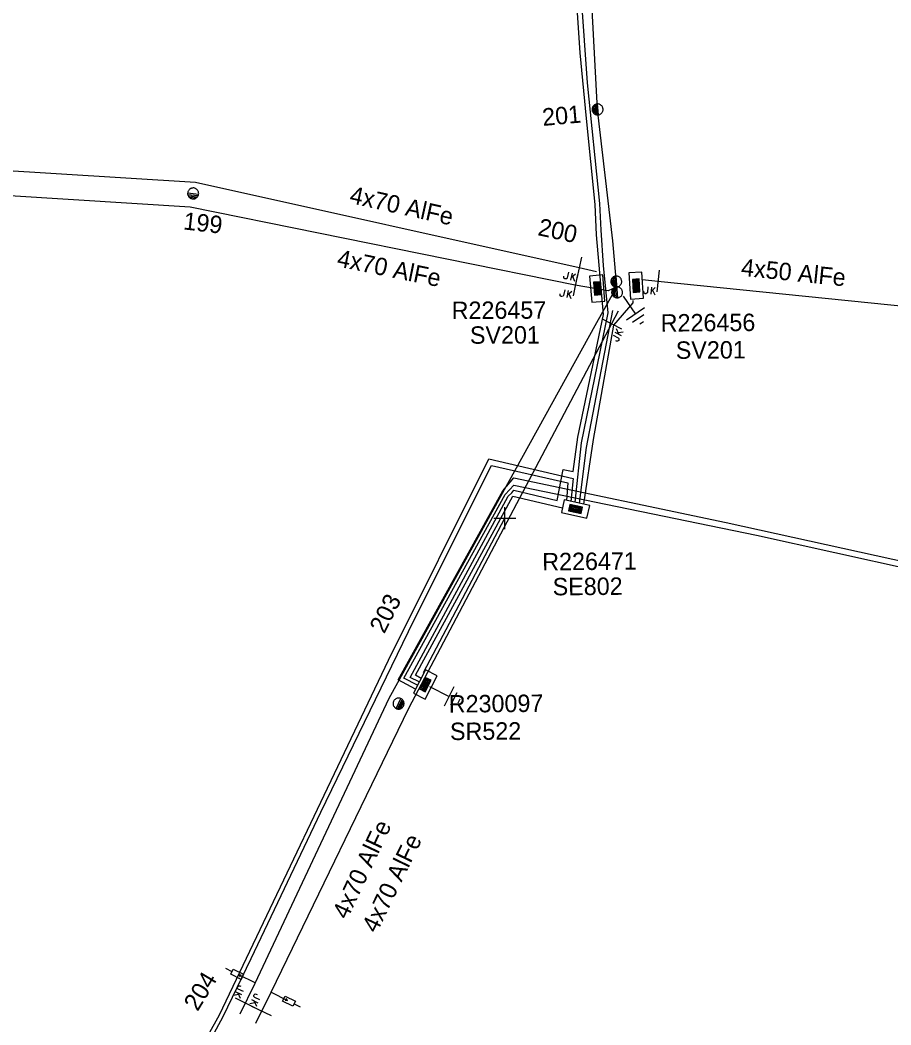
# Model space of a CAD drawing. Extents: x -544780 to -541582, y -1198995 to -1196551.
# Drawn here: x -542503.2 to -542453.2, y -1198617.5 to -1198559.8 of the extents above; entities that cross this region are included whole.
import ezdxf

# ---------------------------------------------------------------- set-up
doc = ezdxf.new("R2010")
doc.units = 0
for name, color, linetype in [('Vrstva 1', 7, 'Continuous'), ('Vrstva 13', 7, 'Continuous'), ('Vrstva 14', 7, 'Continuous'), ('Vrstva 15', 7, 'Continuous'), ('Vrstva 16', 7, 'Continuous'), ('Vrstva 18', 7, 'Continuous'), ('Vrstva 2', 7, 'Continuous'), ('Vrstva 28', 7, 'Continuous'), ('Vrstva 29', 7, 'Continuous'), ('Vrstva 30', 7, 'Continuous'), ('Vrstva 34', 7, 'Continuous'), ('Vrstva 5', 7, 'Continuous'), ('Vrstva 52', 7, 'Continuous'), ('Vrstva 8', 7, 'Continuous')]:
    doc.layers.add(name, color=color, linetype=linetype)

# ---------------------------------------------------------------- blocks, each defined once
blk = doc.blocks.new('NN440')
at = {"layer": 'Vrstva 2'}
for points in [[(0.63, 0), (0.63, 0.06), (0.62, 0.13), (0.6, 0.19), (0.58, 0.25), (0.55, 0.31), (0.51, 0.37), (0.47, 0.42), (0.42, 0.46), (0.37, 0.51), (0.32, 0.54), (0.26, 0.57), (0.2, 0.59), (0.13, 0.61), (0.07, 0.62), (0, 0.63), (-0.06, 0.62), (-0.13, 0.61), (-0.19, 0.59), (-0.26, 0.57), (-0.31, 0.54), (-0.37, 0.51), (-0.42, 0.46), (-0.47, 0.42), (-0.51, 0.37), (-0.54, 0.31), (-0.57, 0.25), (-0.6, 0.19), (-0.62, 0.13), (-0.63, 0.06), (-0.63, 0), (-0.63, -0.07), (-0.62, -0.14), (-0.6, -0.2), (-0.57, -0.26), (-0.54, -0.32), (-0.51, -0.37), (-0.47, -0.43), (-0.42, -0.47), (-0.37, -0.51), (-0.31, -0.55), (-0.26, -0.58), (-0.19, -0.6), (-0.13, -0.62), (-0.06, -0.63), (0, -0.63), (0.07, -0.63), (0.13, -0.62), (0.2, -0.6), (0.26, -0.58), (0.32, -0.55), (0.37, -0.51), (0.42, -0.47), (0.47, -0.43), (0.51, -0.37), (0.55, -0.32), (0.58, -0.26), (0.6, -0.2), (0.62, -0.14), (0.63, -0.07), (0.63, 0)], [(-0.63, 0), (0.63, 0)], [(-0.6, -0.18), (0.57, -0.18)], [(-0.51, -0.32), (0.5, -0.32)], [(-0.37, -0.47), (0.35, -0.47)]]:
    blk.add_lwpolyline(points, dxfattribs=at)
blk = doc.blocks.new('NN450')
at = {"layer": 'Vrstva 2'}
for points in [[(0, 0), (0, 0.07), (-0.01, 0.13), (-0.03, 0.19), (-0.05, 0.25), (-0.08, 0.31), (-0.12, 0.37), (-0.16, 0.42), (-0.21, 0.46), (-0.26, 0.51), (-0.31, 0.54), (-0.37, 0.57), (-0.43, 0.59), (-0.5, 0.61), (-0.56, 0.62), (-0.63, 0.62), (-0.69, 0.62), (-0.75, 0.61), (-0.82, 0.59), (-0.88, 0.57), (-0.94, 0.54), (-0.99, 0.51), (-1.04, 0.46), (-1.09, 0.42), (-1.13, 0.37), (-1.17, 0.31), (-1.2, 0.25), (-1.22, 0.19), (-1.24, 0.13), (-1.25, 0.07), (-1.25, 0), (-1.25, -0.07), (-1.24, -0.13), (-1.22, -0.19), (-1.2, -0.25), (-1.17, -0.31), (-1.13, -0.37), (-1.09, -0.42), (-1.04, -0.46), (-0.99, -0.51), (-0.94, -0.54), (-0.88, -0.57), (-0.82, -0.59), (-0.75, -0.61), (-0.69, -0.62), (-0.62, -0.63), (-0.56, -0.62), (-0.5, -0.61), (-0.43, -0.59), (-0.37, -0.57), (-0.31, -0.54), (-0.26, -0.51), (-0.21, -0.46), (-0.16, -0.42), (-0.12, -0.37), (-0.08, -0.31), (-0.05, -0.25), (-0.03, -0.19), (-0.01, -0.13), (0, -0.07), (0, 0)], [(1.25, 0), (1.25, 0.07), (1.24, 0.13), (1.22, 0.19), (1.2, 0.25), (1.17, 0.31), (1.13, 0.37), (1.09, 0.42), (1.04, 0.46), (0.99, 0.51), (0.94, 0.54), (0.88, 0.57), (0.82, 0.59), (0.75, 0.61), (0.69, 0.62), (0.62, 0.62), (0.56, 0.62), (0.5, 0.61), (0.43, 0.59), (0.37, 0.57), (0.31, 0.54), (0.26, 0.51), (0.21, 0.46), (0.16, 0.42), (0.12, 0.37), (0.08, 0.31), (0.05, 0.25), (0.03, 0.19), (0.01, 0.13), (0, 0.07), (0, 0), (0, -0.07), (0.01, -0.13), (0.03, -0.19), (0.05, -0.25), (0.08, -0.31), (0.12, -0.37), (0.16, -0.42), (0.21, -0.46), (0.26, -0.51), (0.31, -0.54), (0.37, -0.57), (0.43, -0.59), (0.5, -0.61), (0.56, -0.62), (0.63, -0.63), (0.69, -0.62), (0.75, -0.61), (0.82, -0.59), (0.88, -0.57), (0.94, -0.54), (0.99, -0.51), (1.04, -0.46), (1.09, -0.42), (1.13, -0.37), (1.17, -0.31), (1.2, -0.25), (1.22, -0.19), (1.24, -0.13), (1.25, -0.07), (1.25, 0)], [(-1.25, 0), (1.25, 0)], [(-1.23, -0.16), (-0.02, -0.16)], [(-1.16, -0.32), (-0.09, -0.32)], [(-1.03, -0.47), (-0.22, -0.47)], [(0.02, -0.16), (1.23, -0.16)], [(0.09, -0.32), (1.16, -0.32)], [(0.22, -0.47), (1.03, -0.47)]]:
    blk.add_lwpolyline(points, dxfattribs=at)
blk = doc.blocks.new('NN840')
at = {"layer": 'Vrstva 15'}
for points in [[(0.003, 0.619), (0.003, -0.631)], [(-0.538, -0.385), (-0.538, -0.71)], [(-0.332, -0.385), (-0.332, -0.798)], [(-0.332, -0.641), (-0.125, -0.385)], [(-0.263, -0.557), (-0.091, -0.798)], [(-0.745, -0.71), (-0.745, -0.66)], [(-0.73, -0.764), (-0.745, -0.71)], [(-0.657, -0.798), (-0.73, -0.764)], [(-0.627, -0.798), (-0.657, -0.798)], [(-0.558, -0.764), (-0.627, -0.798)], [(-0.538, -0.71), (-0.558, -0.764)]]:
    blk.add_lwpolyline(points, dxfattribs=at)
blk = doc.blocks.new('NN800')
at = {"layer": 'Vrstva 1'}
for points in [[(-0.442, 0.442), (0.442, -0.442)], [(-0.442, -0.442), (0.442, 0.442)]]:
    blk.add_lwpolyline(points, dxfattribs=at)
blk = doc.blocks.new('NN820')
at = {"layer": 'Vrstva 13'}
for points in [[(-0.003, 0.004), (-0.003, -1.049)], [(-0.165, -0.813), (0.165, -0.813)], [(-0.165, -1.473), (-0.165, -0.813)], [(-0.003, -1.049), (-0.062, -0.926)], [(-0.003, -1.049), (0.057, -0.926)], [(0.165, -0.813), (0.165, -1.473)], [(0.165, -1.473), (-0.165, -1.473)], [(-0.003, -1.473), (-0.003, -1.871)]]:
    blk.add_lwpolyline(points, dxfattribs=at)
blk = doc.blocks.new('NN620')
at = {"layer": 'Vrstva 8'}
for points in [[(0.752, 0.004), (-0.748, 0.004)], [(-0.748, 0.004), (-0.748, -0.746)], [(0.752, -0.746), (0.752, 0.004)], [(0.368, -0.18), (-0.376, -0.18)], [(-0.376, -0.18), (-0.376, -0.558)], [(-0.376, -0.558), (0.368, -0.558)], [(0.321, -0.227), (-0.329, -0.227)], [(-0.329, -0.227), (-0.329, -0.51)], [(-0.329, -0.51), (0.321, -0.51)], [(0.274, -0.274), (-0.281, -0.274)], [(-0.281, -0.274), (-0.281, -0.463)], [(-0.281, -0.463), (0.274, -0.463)], [(0.227, -0.321), (-0.234, -0.321)], [(-0.234, -0.321), (-0.234, -0.416)], [(-0.234, -0.416), (0.227, -0.416)], [(-0.193, -0.369), (0.185, -0.369)], [(0.227, -0.416), (0.227, -0.321)], [(0.274, -0.463), (0.274, -0.274)], [(0.321, -0.51), (0.321, -0.227)], [(0.368, -0.558), (0.368, -0.18)], [(-0.748, -0.746), (0.752, -0.746)]]:
    blk.add_lwpolyline(points, dxfattribs=at)
blk = doc.blocks.new('NN810')
at = {"layer": 'Vrstva 14'}
for points in [[(0.004, -0.64), (0.004, -1.89)], [(0.629, -1.89), (-0.621, -1.89)], [(0.388, -2.2), (-0.399, -2.2)], [(0.004, -2.515), (-0.124, -2.515)], [(0.137, -2.515), (0.004, -2.515)]]:
    blk.add_lwpolyline(points, dxfattribs=at)

msp = doc.modelspace()

# ---------------------------------------------------------------- linework, layer by layer
at = {"layer": 'Vrstva 1'}
for points in [[(-542468.937, -1198575.165), (-542469.166, -1198572.51), (-542470.032, -1198564.977), (-542470.578, -1198554.925)], [(-542468.937, -1198575.165), (-542469.418, -1198575.393), (-542471.312, -1198575.063), (-542493.418, -1198570.581), (-542520.821, -1198568.867), (-542547.289, -1198568.867), (-542573.951, -1198565.092), (-542607.008, -1198561.88), (-542636.019, -1198560.809), (-542636.996, -1198560.774)], [(-542470.089, -1198574.29), (-542471.092, -1198574.066), (-542493.107, -1198569.179), (-542520.509, -1198567.465)], [(-542467.456, -1198574.735), (-542466.568, -1198574.826), (-542449.621, -1198576.557), (-542436.372, -1198579.515), (-542423.343, -1198581.048), (-542395.641, -1198584.992), (-542374.333, -1198589.374)], [(-542490.551, -1198616.879), (-542489.69, -1198615.116), (-542482.003, -1198598.772), (-542470.082, -1198577.206), (-542468.937, -1198575.165)], [(-542489.653, -1198617.421), (-542488.766, -1198615.646), (-542480.869, -1198599.347), (-542468.84, -1198576.539)]]:
    msp.add_lwpolyline(points, dxfattribs=at)
at = {"layer": 'Vrstva 5'}
for points in [[(-542480.281, -1198597.836), (-542480.799, -1198597.58), (-542475.157, -1198587.174), (-542474.962, -1198586.979), (-542474.841, -1198586.833), (-542472.359, -1198587.417), (-542472.011, -1198585.635), (-542471.444, -1198585.756), (-542471.171, -1198583.794), (-542469.689, -1198576.743), (-542470.102, -1198572.18), (-542470.175, -1198570.429), (-542470.661, -1198565.504), (-542471.025, -1198561.735), (-542471.536, -1198554.257), (-542469.786, -1198554.159)], [(-542471.319, -1198587.525), (-542470.952, -1198584.11), (-542469.421, -1198576.646), (-542469.689, -1198573.931), (-542469.834, -1198571.913), (-542469.907, -1198570.383), (-542470.612, -1198563.443), (-542471.122, -1198556.149), (-542471.171, -1198553.969), (-542469.81, -1198553.872)], [(-542470.82, -1198587.636), (-542470.272, -1198583.912), (-542469.105, -1198577.355), (-542467.996, -1198576.068), (-542467.998, -1198575.935)], [(-542471.068, -1198587.579), (-542470.661, -1198584.378), (-542469.158, -1198576.525)], [(-542484.072, -1198642.566), (-542501.191, -1198635.632), (-542494.981, -1198622.783), (-542491.725, -1198616.948), (-542482.038, -1198596.585), (-542476.266, -1198585.023), (-542471.428, -1198586.153), (-542471.567, -1198587.471)], [(-542484.042, -1198642.27), (-542500.865, -1198635.484), (-542497.636, -1198628.837), (-542495.089, -1198623.592), (-542493.441, -1198620.587), (-542491.516, -1198617.031), (-542489.917, -1198613.712), (-542485.918, -1198605.313), (-542480.587, -1198594.303), (-542476.126, -1198585.416), (-542471.735, -1198586.413), (-542471.819, -1198587.417)], [(-542480.489, -1198598.259), (-542481.478, -1198597.718), (-542475.48, -1198586.87), (-542474.848, -1198586.116), (-542462.649, -1198588.693), (-542441.447, -1198593.362), (-542417.555, -1198596.786), (-542417.319, -1198595.161), (-542417.246, -1198594.966), (-542410.733, -1198596.133), (-542397.624, -1198598.37), (-542381.307, -1198601.233), (-542362.61, -1198604.536), (-542349.307, -1198606.915), (-542336.927, -1198609.151), (-542337.121, -1198610.221)], [(-542480.374, -1198598.027), (-542481.153, -1198597.621), (-542475.342, -1198587.07), (-542474.831, -1198586.535), (-542469.558, -1198587.63), (-542460.907, -1198589.405), (-542451.924, -1198591.398)], [(-542480.164, -1198597.63), (-542480.476, -1198597.439), (-542474.889, -1198587.17), (-542472.054, -1198587.837)]]:
    msp.add_lwpolyline(points, dxfattribs=at)
at = {"layer": 'Vrstva 52'}
msp.add_lwpolyline([(-542480.026, -1198597.289), (-542475.355, -1198588.438)], dxfattribs=at)

# ---------------------------------------------------------------- block references
at = {"layer": 'Vrstva 13'}
for name, p, xscale, yscale, rotation in [('NN440', (-542470.032, -1198564.977), 0.49999999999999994, 0.5000000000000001, -84.91075002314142), ('NN440', (-542493.244, -1198569.797), 0.5, 0.5, -6.524602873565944), ('NN450', (-542468.937, -1198575.165), 0.5, 0.5, -85.85884440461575), ('NN440', (-542481.459, -1198599.079), 0.5000000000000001, 0.5000000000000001, 63.98582776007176)]:
    msp.add_blockref(name, p, dxfattribs=dict(at, xscale=xscale, yscale=yscale, rotation=rotation))
at = {"layer": 'Vrstva 15'}
for p, rotation in [((-542468.938, -1198575.165), 34.452369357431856), ((-542480.25, -1198597.82), 63.23083060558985)]:
    msp.add_blockref('NN810', p, dxfattribs=dict(at, rotation=rotation))
at = {"layer": 'Vrstva 16'}
for p, rotation in [((-542489.69, -1198615.116), -116.04254448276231), ((-542488.766, -1198615.646), 63.455255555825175)]:
    msp.add_blockref('NN820', p, dxfattribs=dict(at, rotation=rotation))
at = {"layer": 'Vrstva 18'}
for p, rotation in [((-542471.092, -1198574.066), -12.51805277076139), ((-542471.312, -1198575.063), -11.462030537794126), ((-542466.568, -1198574.826), -5.832597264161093), ((-542469.227, -1198577.285), 62.54138613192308), ((-542490.251, -1198616.264), -116.04254448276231), ((-542489.309, -1198616.735), -115.84929448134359)]:
    msp.add_blockref('NN840', p, dxfattribs=dict(at, rotation=rotation))
at = {"layer": 'Vrstva 28'}
for p, rotation in [((-542469.685, -1198575.225), -85.38000000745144), ((-542468.188, -1198575.113), 93.94400004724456), ((-542471.22, -1198587.548), -12.2806918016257), ((-542480.25, -1198597.82), 63.23083060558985)]:
    msp.add_blockref('NN620', p, dxfattribs=dict(at, rotation=rotation))
at = {"layer": 'Vrstva 34', "rotation": 45}
msp.add_blockref('NN800', (-542475.355, -1198588.438), dxfattribs=at)

# ---------------------------------------------------------------- texts
at = {"layer": 'Vrstva 14'}
for s, rotation, p in [('201', 5.089, (-542473.166, -1198565.926)), ('199', 353.475, (-542493.843, -1198571.859)), ('200', 347.833, (-542473.512, -1198572.186)), ('203', 63.231, (-542482.276, -1198595.114)), ('204', 58.693, (-542492.989, -1198616.787))]:
    msp.add_text(s, height=1, rotation=rotation, dxfattribs=at).set_placement(p)
at = {"layer": 'Vrstva 2'}
for s, rotation, p in [('4x70 AlFe', 347.484, (-542484.321, -1198570.336)), ('4x70 AlFe', 348.539, (-542485.039, -1198573.977)), ('4x50 AlFe', 354.168, (-542461.832, -1198574.52)), ('4x70 AlFe', 64.811, (-542484.399, -1198611.519)), ('4x70 AlFe', 64.149, (-542482.712, -1198612.301))]:
    msp.add_text(s, height=1, rotation=rotation, dxfattribs=at).set_placement(p)
at = {"layer": 'Vrstva 29'}
for s, rotation, p in [('R226457', 0.229, (-542478.406, -1198577.008)), ('R226456', 0.38, (-542466.408, -1198577.731)), ('R226471', 0.492, (-542473.207, -1198591.435)), ('R230097', 0.435, (-542478.571, -1198599.596))]:
    msp.add_text(s, height=1, rotation=rotation, dxfattribs=at).set_placement(p)
at = {"layer": 'Vrstva 30'}
for s, rotation, p in [('SV201', 0.229, (-542477.358, -1198578.429)), ('SV201', 0.38, (-542465.542, -1198579.293)), ('SE802', 0.492, (-542472.607, -1198592.869)), ('SR522', 0.435, (-542478.501, -1198601.174))]:
    msp.add_text(s, height=1, rotation=rotation, dxfattribs=at).set_placement(p)

doc.saveas('drawing.dxf')
